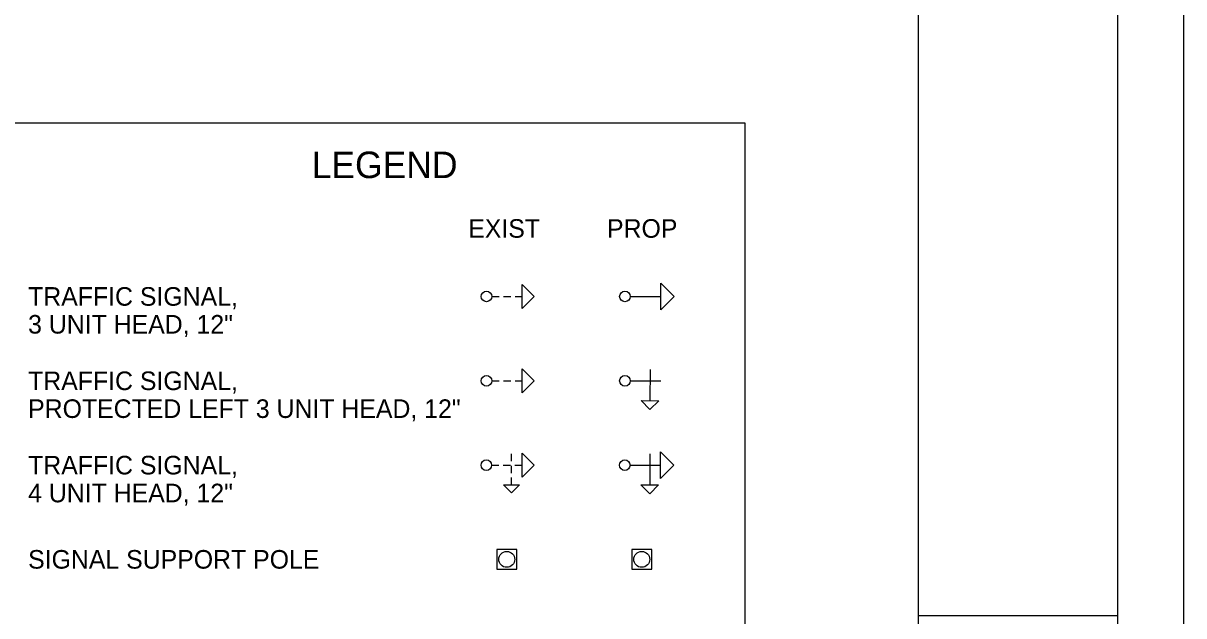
# Model space of a CAD drawing. Extents: x -32.9 to 34, y 0 to 22.3.
# Drawn here: x 25.25 to 34, y 4.5 to 8.96 of the extents above; entities that cross this region are included whole.
import ezdxf

# ---------------------------------------------------------------- set-up
doc = ezdxf.new("R2010")
doc.units = 0
for name, color, linetype in [('GE_P_Alignment', 7, 'Continuous'), ('GE_P_Driveway_CL', 7, 'Continuous'), ('PF_X_Ground_Line', 7, 'Continuous'), ('PV_P_Curb_Ramp', 7, 'Continuous'), ('PV_P_Saw_Cut_Line', 7, 'Continuous')]:
    doc.layers.add(name, color=color, linetype=linetype)

msp = doc.modelspace()

# ---------------------------------------------------------------- linework, layer by layer
at = {"layer": 'GE_P_Alignment'}
msp.add_lwpolyline([(0, 0), (34, 0), (34, 22), (0, 22)], close=True, dxfattribs=at)
at = {"layer": 'GE_P_Driveway_CL'}
for p, q in [((29.9777, 6.3544), (29.9768, 6.1194)), ((29.8281, 6.2691), (30.0581, 6.2683))]:
    msp.add_line(p, q, dxfattribs=at)
msp.add_lwpolyline([(30.0432, 6.1194), (29.9763, 6.053), (29.9099, 6.1199)], close=True, dxfattribs=at)
msp.add_circle((29.7881, 6.2693), 0.04, dxfattribs=at)
at = {"layer": 'PF_X_Ground_Line'}
for p, q in [((28.7846, 6.9051), (28.8396, 6.9051)), ((28.8721, 6.9051), (28.9271, 6.9051)), ((28.9596, 6.9051), (29.0146, 6.9051)), ((29.8281, 6.9051), (30.0581, 6.9051)), ((28.7846, 6.2693), (28.8396, 6.2693)), ((28.8721, 6.2693), (28.9271, 6.2693)), ((28.9596, 6.2693), (29.0146, 6.2693)), ((28.9326, 5.6643), (28.9326, 5.7193)), ((29.976, 5.7193), (29.976, 5.4843)), ((28.7833, 5.6335), (28.8383, 5.6335)), ((28.8708, 5.6335), (28.9258, 5.6335)), ((28.9326, 5.5743), (28.9326, 5.6293)), ((28.9583, 5.6335), (29.0133, 5.6335)), ((29.8268, 5.6335), (30.0568, 5.6335)), ((28.9326, 5.4843), (28.9326, 5.5393))]:
    msp.add_line(p, q, dxfattribs=at)
for points in [[(30.0579, 7.005), (30.1579, 6.905), (30.0579, 6.805)], [(29.0146, 6.9951), (29.1046, 6.9051), (29.0146, 6.8151)], [(29.0146, 6.3593), (29.1046, 6.2693), (29.0146, 6.1793)], [(29.0133, 5.7235), (29.1033, 5.6335), (29.0133, 5.5435)], [(30.0563, 5.7338), (30.1563, 5.6338), (30.0563, 5.5338)], [(28.9926, 5.4843), (28.9326, 5.4243), (28.8726, 5.4843)], [(30.0416, 5.4846), (29.9749, 5.418), (29.9083, 5.4846)], [(28.8222, 4.8485), (28.9722, 4.8485), (28.9722, 4.9985), (28.8222, 4.9985)], [(29.8397, 4.8485), (29.9897, 4.8485), (29.9897, 4.9985), (29.8397, 4.9985)]]:
    msp.add_lwpolyline(points, close=True, dxfattribs=at)
for centre, radius in [((28.7446, 6.9051), 0.04), ((29.7881, 6.9051), 0.04), ((28.7446, 6.2693), 0.04), ((28.7433, 5.6335), 0.04), ((29.7868, 5.6335), 0.04), ((28.8972, 4.9235), 0.06), ((29.9147, 4.9235), 0.06), ((29.9147, 4.9235), 0.06)]:
    msp.add_circle(centre, radius, dxfattribs=at)
at = {"layer": 'PV_P_Curb_Ramp'}
for p, q in [((32, 0.5), (32, 21.5)), ((32, 4.5), (33.5, 4.5))]:
    msp.add_line(p, q, dxfattribs=at)
msp.add_lwpolyline([(1.5, 21.5), (33.5, 21.5), (33.5, 0.5), (1.5, 0.5)], close=True, dxfattribs=at)
at = {"layer": 'PV_P_Saw_Cut_Line'}
msp.add_lwpolyline([(25.1759, 8.2113), (25.1759, 1.0264), (30.6953, 1.0264), (30.6953, 7.4577), (30.6953, 8.2113)], close=True, dxfattribs=at)

# ---------------------------------------------------------------- texts
at = {"layer": 'PF_X_Ground_Line'}
for s, height, p in [('LEGEND', 0.2, (27.4266, 7.797)), ('EXIST', 0.14, (28.607, 7.3475)), ('PROP', 0.14, (29.6529, 7.3475)), ('TRAFFIC SIGNAL, ', 0.14, (25.2899, 6.8351)), ('3 UNIT HEAD, 12"', 0.14, (25.2899, 6.6251)), ('TRAFFIC SIGNAL, ', 0.14, (25.2899, 6.1993)), ('PROTECTED LEFT 3 UNIT HEAD, 12"', 0.14, (25.2899, 5.9893)), ('TRAFFIC SIGNAL,', 0.14, (25.2899, 5.5635)), ('4 UNIT HEAD, 12"', 0.14, (25.2899, 5.3535)), ('SIGNAL SUPPORT POLE', 0.14, (25.2899, 4.8535))]:
    msp.add_text(s, height=height, dxfattribs=at).set_placement(p)

doc.saveas('drawing.dxf')
